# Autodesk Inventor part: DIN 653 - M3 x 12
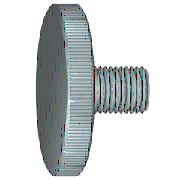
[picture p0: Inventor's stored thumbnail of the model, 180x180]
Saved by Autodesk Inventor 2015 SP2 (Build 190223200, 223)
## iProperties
Created: 2012-02
Part Number: DIN 653 - M3 x 12
Material: Stahl, weich
Description: Rändelschraube
Document SubType Name: Modeling
Standard: DIN 653
Designer: rYan
Standards Organization: DIN
Language: de-DE
Size Designation: M3 x 12
Categories: <MemberInstance><Categories><Category DisplayName="Verbindungselemente" InternalName="e4da775c-781d-43d5-af7c-5136215cf5a6" Mnemonic="FSTN"><Category DisplayNam
Density: 7.85 g/cm^3
Appearance: Halbpoliert
IsCustomPart: 0
Author: rYan
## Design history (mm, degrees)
revolve "Körper" stored, may be unused: angle "d8" = 90 deg
node "IDS_WORKPLANE{1}"
workplane "Work Plane2"
body "Solid1"
feature "Gewinde" dims "d2" = 8.224 (= GEL - 0.092 x GD), "d3" = 0
chamfer "Fase1" distance "d10" = 0.3 (= PHH); stored, may be unused: angle "d11" = 45 deg (= FAWI), second distance "d38" = 0.3 (= PHH)
sketch "Skizze1"
  geometry: L1 (-2.5, 0)-(12, 0); L2 (12, 0)-(12, 5); L3 (11.673, 1.5)-(0, 1.5); L4 (0, -1.2)-(0, 7.2) reference; L5 (0, 1.5)-(0, 6); L6 (0, 6)-(-2.5, 6); L7 (-2.5, 6)-(-2.5, 0); L8 (-5.416, 0)-(14.997, 0) reference; A1 r 3.6 centre (8.4, 0) between (12, 0) and (11.673, 1.5)
  constraints: 13 end point, 2 perpendicular, 2 point on circle, 2 vertical alignment, 1 centre point, 1 collinear, 1 parallel, 1 point on line, 1 tangent
  dimensions: "d1" = 3 diameter of L3 L1 (= GD); "d6" = 12 diameter of L6 L1 (= KOD); "d7" = 2.5 distance between parallel lines of L5 L7 (= KOH); "d9" = 3.6 radius of A1 (= 1.2 x GD); "d41" = 12 distance between parallel lines of L2 L5 (= NLG)
other parameters: "GD" = 3 [user parameter; used in 3 equation terms], "NLG" = 12 [user parameter; used in 1 equation term], "GEL" = 8.5 [user parameter; used in 1 equation term], "KOD" = 12 [user parameter; used in 1 equation term], "KOH" = 2.5 [user parameter; used in 2 equation terms], "GAL" = 0.30673 (= 0.61345 x PTC) [user parameter], "d4" = 0, "SD" = 2 [user parameter], "LADI" = 3 (= NND) [user parameter], "PHH" = 0.3 [user parameter; used in 2 equation terms], "FAWI" = 45 deg [user parameter; used in 1 equation term], "d12" = -1.25 (= -0.5 x KOH), "T" = 0.5 [user parameter], "d39" = 0, "d42" = 0, "NND" = 3 [user parameter; used in 1 equation term], "PTC" = 0.5 [user parameter; used in 2 equation terms]
